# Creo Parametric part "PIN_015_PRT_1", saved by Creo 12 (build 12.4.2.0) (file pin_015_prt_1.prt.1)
Units: Custom; MM, KILOGRAM, SECS

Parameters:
  PTC_WM_ITERATION = "0"
  PTC_WM_VERSION = "-.0"
  PTC_WM_LIFECYCLE_STATE = "In Work"
  PTC_WM_LIFECYCLE = "MO_CADDocument"
  PTC_WM_CREATED_BY = "Maximilian Roepper (Z0017RMS: MO)"
  PTC_WM_CREATED_ON = "18-Sep-26 11:36:42 AM"
  PTC_WM_MODIFIED_BY = "Maximilian Roepper (Z0017RMS: MO)"
  PTC_WM_MODIFIED_ON = "18-Sep-26 11:36:46 AM"
  PDMLINKNUMBER = "PDM000071455279"
  PTC_WM_NAME = "pin_015_prt_1.prt"
  PTC_WM_NUMBER = "PDM000071455279"

Other parameters: WEIGHT, WEIGHT_FACTOR, WEIGHT_ADD, _MASS_TEMP, _DIFF_TEMP, MC_ERRORS, SUPPLIER

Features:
  1. coordinate system
  2. datum plane "PRT_YZ"
  3. datum plane "PRT_XY"
  4. datum plane "PRT_XZ"
  5. coordinate system
  6. datum axis
  7. datum axis
  8. datum axis
  9. coordinate system
  10. imported feature
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
Other named items: PRT, SIEMENS_MO, DRW_VIEW_ORG, PRT_X, PRT_Y, PRT_Z, CS0, ROUGH_GROB

Layers: 00_STD_CSYS-KSYS, 01_STD_PLANES-EBENEN, 02_STD_AXES-ACHSEN, 03_STD_CSYS-KSYS, 24_IMPORT_FEAT-IMPORT_KE

Surfaces: 9 plane, 1 cylinder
